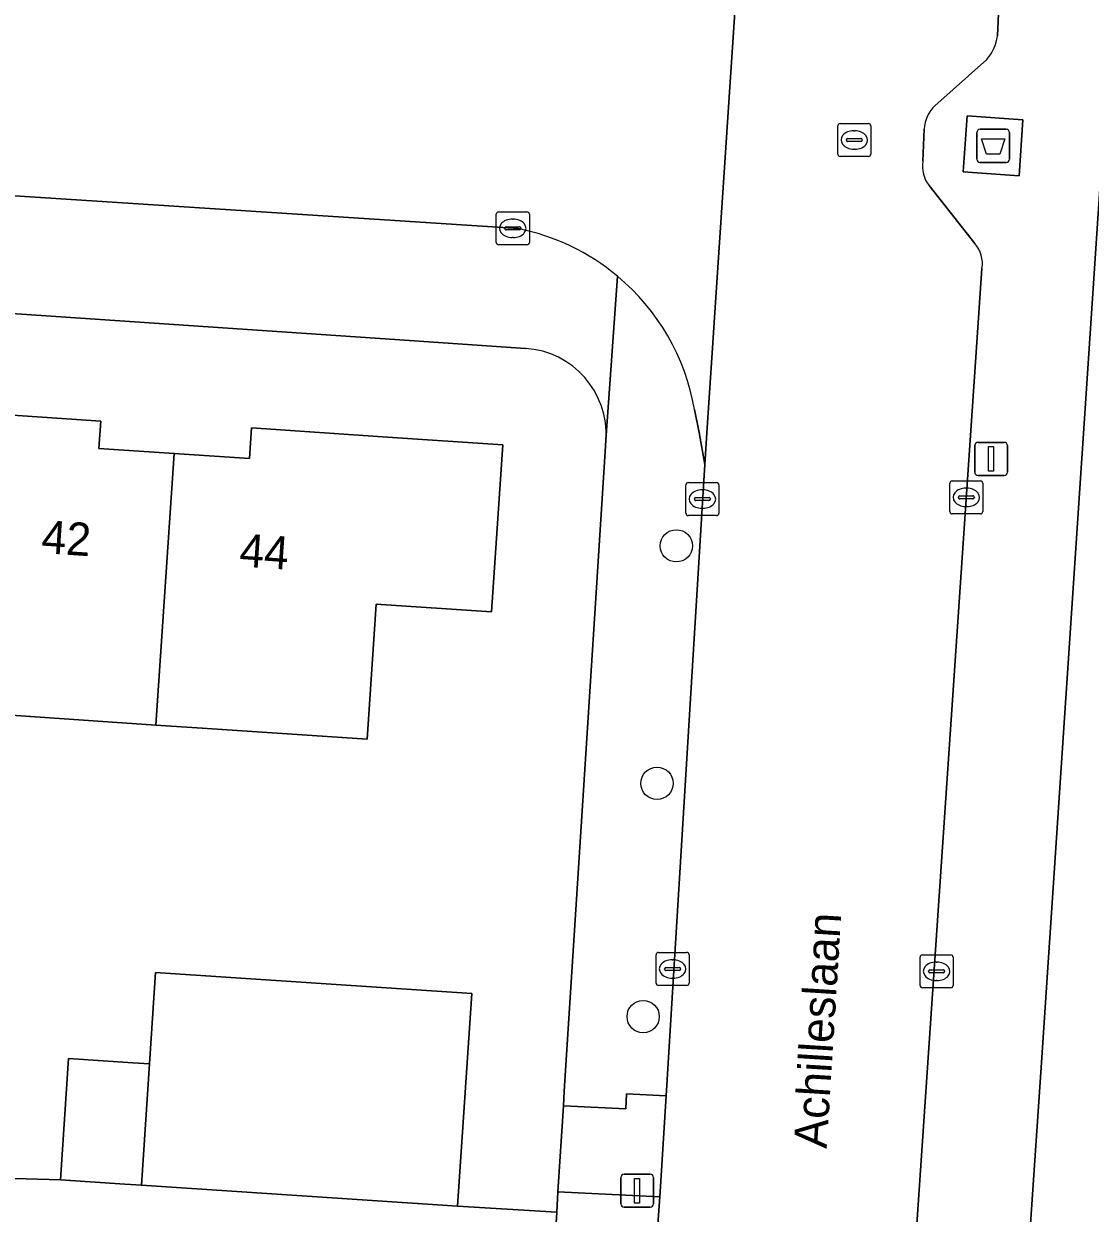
# Model space of a CAD drawing. Extents: x 161848 to 162726, y 385382 to 386521.
# Drawn here: x 162412.92 to 162445.21, y 385424.82 to 385460.85 of the extents above; entities that cross this region are included whole.
import ezdxf

# ---------------------------------------------------------------- set-up
doc = ezdxf.new("R2010")
doc.units = 0
for name, color, linetype in [('IMGEO_Afval_apart_plaats', 7, 'Continuous'), ('IMGEO_Boom', 7, 'Continuous'), ('IMGEO_Erf', 7, 'Continuous'), ('IMGEO_Groenvoorziening', 7, 'Continuous'), ('IMGEO_Kolk', 7, 'Continuous'), ('IMGEO_Lichtmast', 7, 'Continuous'), ('IMGEO_Muur', 7, 'Continuous'), ('IMGEO_Openbare_ruimte_label', 7, 'Continuous'), ('IMGEO_Pand', 7, 'Continuous'), ('IMGEO_Pand_nummerreeks', 7, 'Continuous'), ('IMGEO_Rijbaan_lokaal_gesloten', 7, 'Continuous'), ('IMGEO_Rijbaan_lokaal_open', 7, 'Continuous'), ('IMGEO_Rioolput', 7, 'Continuous'), ('IMGEO_Voetpad_gesloten', 7, 'Continuous'), ('IMGEO_Voetpad_open', 7, 'Continuous')]:
    doc.layers.add(name, color=color, linetype=linetype)

msp = doc.modelspace()

# ---------------------------------------------------------------- linework, layer by layer
at = {"layer": 'IMGEO_Afval_apart_plaats'}
for p, q in [((162441.772, 385456.749), (162441.772, 385457.549)), ((162441.772, 385457.549), (162441.772, 385456.749)), ((162441.872, 385457.649), (162442.662, 385457.649)), ((162442.662, 385457.649), (162441.872, 385457.649)), ((162442.762, 385457.549), (162442.762, 385456.749)), ((162442.762, 385456.749), (162442.762, 385457.549)), ((162442.662, 385456.649), (162441.872, 385456.649)), ((162441.872, 385456.649), (162442.662, 385456.649))]:
    msp.add_line(p, q, dxfattribs=at)
msp.add_lwpolyline([(162441.915, 385457.363), (162442.619, 385457.363), (162442.47, 385456.893), (162442.064, 385456.893), (162441.915, 385457.363)], dxfattribs=at)
for centre, start, end in [((162441.872, 385457.549), 90, 180), ((162441.872, 385457.549), 90, 180), ((162442.662, 385457.549), 0, 90), ((162442.662, 385457.549), 360, 90), ((162441.872, 385456.749), 180, 270), ((162441.872, 385456.749), 180, 270), ((162442.662, 385456.749), 270, 0), ((162442.662, 385456.749), 270, 0)]:
    msp.add_arc(centre, 0.1, start, end, dxfattribs=at)
at = {"layer": 'IMGEO_Boom'}
for centre in [(162432.675, 385445.035), (162432.091, 385437.842), (162431.671, 385430.777)]:
    msp.add_circle(centre, 0.489, dxfattribs=at)
at = {"layer": 'IMGEO_Erf'}
for points in [[(162428.108, 385451.016), (162424.152, 385451.285), (162286.568, 385460.627), (162285.504, 385460.702)], [(162411.535, 385449.066), (162415.25, 385448.815), (162415.193, 385447.986), (162417.472, 385447.832), (162419.751, 385447.678), (162419.813, 385448.605), (162423.927, 385448.327), (162427.421, 385448.092), (162427.08, 385443.035), (162423.586, 385443.271), (162423.309, 385439.175), (162418.321, 385439.513), (162416.914, 385439.608), (162410.92, 385440.013)], [(162409.861, 385425.954), (162414.028, 385425.832), (162414.273, 385429.51), (162416.22, 385429.38), (162416.721, 385429.347), (162416.905, 385432.115), (162426.479, 385431.478), (162426.05, 385425.033), (162429.053, 385424.859), (162429.088, 385425.47), (162429.255, 385428.076), (162429.283, 385428.519), (162430.198, 385442.824), (162430.523, 385447.896), (162430.545, 385448.238)]]:
    msp.add_lwpolyline(points, dxfattribs=at)
msp.add_arc((162427.935, 385448.406), 2.616, 356.3175, 86.2002, dxfattribs=at)
at = {"layer": 'IMGEO_Groenvoorziening'}
msp.add_lwpolyline([(162442.468, 385394.33), (162457.836, 385394.534), (162458.175, 385399.31), (162453.986, 385399.573), (162458.022, 385457.834), (162445.688, 385458.726), (162443.737, 385429.387), (162442.256, 385407.756), (162441.458, 385395.367)], dxfattribs=at)
at = {"layer": 'IMGEO_Kolk'}
for p, q in [((162427.298, 385455.151), (162428.15, 385455.151)), ((162427.223, 385454.225), (162427.223, 385455.077)), ((162427.711, 385454.931), (162427.736, 385454.931)), ((162428.224, 385455.077), (162428.224, 385454.225)), ((162427.482, 385454.645), (162427.482, 385454.657)), ((162427.92, 385454.608), (162427.522, 385454.608)), ((162427.525, 385454.694), (162427.923, 385454.694)), ((162427.966, 385454.657), (162427.966, 385454.645)), ((162428.15, 385454.151), (162427.298, 385454.151)), ((162427.734, 385454.371), (162427.709, 385454.371)), ((162432.965, 385446.026), (162432.965, 385446.878)), ((162433.04, 385446.952), (162433.892, 385446.952)), ((162433.966, 385446.878), (162433.966, 385446.026)), ((162440.956, 385446.077), (162440.956, 385446.929)), ((162441.031, 385447.003), (162441.883, 385447.003)), ((162441.957, 385446.929), (162441.957, 385446.077)), ((162433.267, 385446.495), (162433.665, 385446.495)), ((162433.453, 385446.732), (162433.478, 385446.732)), ((162441.215, 385446.497), (162441.215, 385446.509)), ((162441.258, 385446.546), (162441.656, 385446.546)), ((162441.444, 385446.783), (162441.469, 385446.783)), ((162441.699, 385446.509), (162441.699, 385446.497)), ((162433.224, 385446.446), (162433.224, 385446.458)), ((162433.662, 385446.409), (162433.264, 385446.409)), ((162433.476, 385446.172), (162433.451, 385446.172)), ((162433.708, 385446.458), (162433.708, 385446.446)), ((162441.653, 385446.46), (162441.255, 385446.46)), ((162441.467, 385446.223), (162441.442, 385446.223)), ((162433.892, 385445.952), (162433.04, 385445.952)), ((162441.883, 385446.003), (162441.031, 385446.003)), ((162432.06, 385431.794), (162432.06, 385432.646)), ((162432.135, 385432.72), (162432.987, 385432.72)), ((162432.548, 385432.5), (162432.573, 385432.5)), ((162433.061, 385432.646), (162433.061, 385431.794)), ((162440.054, 385431.723), (162440.054, 385432.575)), ((162440.129, 385432.649), (162440.981, 385432.649)), ((162441.055, 385432.575), (162441.055, 385431.723)), ((162432.319, 385432.214), (162432.319, 385432.226)), ((162432.757, 385432.177), (162432.359, 385432.177)), ((162432.362, 385432.263), (162432.76, 385432.263)), ((162432.803, 385432.226), (162432.803, 385432.214)), ((162440.313, 385432.143), (162440.313, 385432.155)), ((162440.751, 385432.106), (162440.353, 385432.106)), ((162440.356, 385432.192), (162440.754, 385432.192)), ((162440.542, 385432.429), (162440.567, 385432.429)), ((162440.797, 385432.155), (162440.797, 385432.143)), ((162432.987, 385431.72), (162432.135, 385431.72)), ((162432.571, 385431.94), (162432.546, 385431.94)), ((162440.565, 385431.869), (162440.54, 385431.869)), ((162440.981, 385431.649), (162440.129, 385431.649))]:
    msp.add_line(p, q, dxfattribs=at)
for points in [[(162427.298, 385455.151), (162428.15, 385455.151)], [(162427.223, 385454.225), (162427.223, 385455.077)], [(162428.224, 385455.077), (162428.224, 385454.225)], [(162428.15, 385454.151), (162427.298, 385454.151)], [(162432.965, 385446.026), (162432.965, 385446.878)], [(162433.04, 385446.952), (162433.892, 385446.952)], [(162433.966, 385446.878), (162433.966, 385446.026)], [(162440.956, 385446.077), (162440.956, 385446.929)], [(162441.031, 385447.003), (162441.883, 385447.003)], [(162441.957, 385446.929), (162441.957, 385446.077)], [(162433.892, 385445.952), (162433.04, 385445.952)], [(162441.883, 385446.003), (162441.031, 385446.003)], [(162432.06, 385431.794), (162432.06, 385432.646)], [(162432.135, 385432.72), (162432.987, 385432.72)], [(162433.061, 385432.646), (162433.061, 385431.794)], [(162440.054, 385431.723), (162440.054, 385432.575)], [(162440.129, 385432.649), (162440.981, 385432.649)], [(162441.055, 385432.575), (162441.055, 385431.723)], [(162432.987, 385431.72), (162432.135, 385431.72)], [(162440.981, 385431.649), (162440.129, 385431.649)]]:
    msp.add_lwpolyline(points, dxfattribs=at)
for centre, radius, start, end in [((162427.3, 385455.075), 0.0765, 91.552, 178.448), ((162427.3, 385455.075), 0.0765, 91.552, 178.448), ((162428.148, 385455.075), 0.0765, 1.552, 88.448), ((162428.148, 385455.075), 0.0765, 1.552, 88.448), ((162427.522, 385454.654), 0.0403, 85.8775, 175.7526), ((162427.519, 385454.644), 0.0366, 178.938, 274.7102), ((162427.923, 385454.651), 0.043, 264.8664, 352.4533), ((162427.927, 385454.656), 0.0386, 1.7309, 96.639), ((162427.3, 385454.227), 0.0765, 181.552, 268.448), ((162427.3, 385454.227), 0.0765, 181.552, 268.448), ((162428.148, 385454.227), 0.0765, 271.552, 358.448), ((162428.148, 385454.227), 0.0765, 271.552, 358.448), ((162433.042, 385446.876), 0.0765, 91.552, 178.448), ((162433.042, 385446.876), 0.0765, 91.552, 178.448), ((162433.89, 385446.876), 0.0765, 1.552, 88.448), ((162433.89, 385446.876), 0.0765, 1.552, 88.448), ((162441.033, 385446.927), 0.0765, 91.552, 178.448), ((162441.033, 385446.927), 0.0765, 91.552, 178.448), ((162441.881, 385446.927), 0.0765, 1.552, 88.448), ((162441.881, 385446.927), 0.0765, 1.552, 88.448), ((162433.264, 385446.455), 0.0403, 85.8775, 175.7526), ((162433.669, 385446.457), 0.0386, 1.7309, 96.639), ((162441.255, 385446.506), 0.0403, 85.8775, 175.7526), ((162441.252, 385446.496), 0.0366, 178.938, 274.7102), ((162441.656, 385446.503), 0.043, 264.8664, 352.4533), ((162441.66, 385446.508), 0.0386, 1.7309, 96.639), ((162433.261, 385446.445), 0.0366, 178.938, 274.7102), ((162433.665, 385446.452), 0.043, 264.8664, 352.4533), ((162433.042, 385446.028), 0.0765, 181.552, 268.448), ((162433.042, 385446.028), 0.0765, 181.552, 268.448), ((162433.89, 385446.028), 0.0765, 271.552, 358.448), ((162433.89, 385446.028), 0.0765, 271.552, 358.448), ((162441.033, 385446.079), 0.0765, 181.552, 268.448), ((162441.033, 385446.079), 0.0765, 181.552, 268.448), ((162441.881, 385446.079), 0.0765, 271.552, 358.448), ((162441.881, 385446.079), 0.0765, 271.552, 358.448), ((162432.137, 385432.644), 0.0765, 91.552, 178.448), ((162432.137, 385432.644), 0.0765, 91.552, 178.448), ((162432.985, 385432.644), 0.0765, 1.552, 88.448), ((162432.985, 385432.644), 0.0765, 1.552, 88.448), ((162440.131, 385432.573), 0.0765, 91.552, 178.448), ((162440.131, 385432.573), 0.0765, 91.552, 178.448), ((162440.979, 385432.573), 0.0765, 1.552, 88.448), ((162440.979, 385432.573), 0.0765, 1.552, 88.448), ((162432.359, 385432.223), 0.0403, 85.8775, 175.7526), ((162432.356, 385432.213), 0.0366, 178.938, 274.7102), ((162432.76, 385432.22), 0.043, 264.8664, 352.4533), ((162432.764, 385432.225), 0.0386, 1.7309, 96.639), ((162440.353, 385432.152), 0.0403, 85.8775, 175.7526), ((162440.35, 385432.142), 0.0366, 178.938, 274.7102), ((162440.754, 385432.149), 0.043, 264.8664, 352.4533), ((162440.758, 385432.154), 0.0386, 1.7309, 96.639), ((162432.137, 385431.796), 0.0765, 181.552, 268.448), ((162432.137, 385431.796), 0.0765, 181.552, 268.448), ((162432.985, 385431.796), 0.0765, 271.552, 358.448), ((162432.985, 385431.796), 0.0765, 271.552, 358.448), ((162440.131, 385431.725), 0.0765, 181.552, 268.448), ((162440.131, 385431.725), 0.0765, 181.552, 268.448), ((162440.979, 385431.725), 0.0765, 271.552, 358.448), ((162440.979, 385431.725), 0.0765, 271.552, 358.448)]:
    msp.add_arc(centre, radius, start, end, dxfattribs=at)
for centre, major_axis, ratio, start_param, end_param in [((162427.71, 385454.651), (-0.387, 0.002), 0.722429, 4.712389, 7.853982), ((162427.735, 385454.651), (-0.39, 0.002), 0.717154, 1.570796, 4.712389), ((162433.452, 385446.452), (-0.387, 0.002), 0.722429, 4.712389, 7.853982), ((162433.477, 385446.452), (-0.39, 0.002), 0.717154, 1.570796, 4.712389), ((162441.443, 385446.503), (-0.387, 0.002), 0.722429, 4.712389, 7.853982), ((162441.468, 385446.503), (-0.39, 0.002), 0.717154, 1.570796, 4.712389), ((162432.547, 385432.22), (-0.387, 0.002), 0.722429, 4.712389, 7.853982), ((162432.572, 385432.22), (-0.39, 0.002), 0.717154, 1.570796, 4.712389), ((162440.541, 385432.149), (-0.387, 0.002), 0.722429, 4.712389, 7.853982), ((162440.566, 385432.149), (-0.39, 0.002), 0.717154, 1.570796, 4.712389)]:
    msp.add_ellipse(centre, major_axis=major_axis, ratio=ratio, start_param=start_param, end_param=end_param, dxfattribs=at)
at = {"layer": 'IMGEO_Lichtmast'}
for p, q in [((162441.711, 385447.269), (162441.711, 385448.069)), ((162441.711, 385448.069), (162441.711, 385447.269)), ((162441.811, 385448.169), (162442.601, 385448.169)), ((162442.601, 385448.169), (162441.811, 385448.169)), ((162442.701, 385448.069), (162442.701, 385447.269)), ((162442.701, 385447.269), (162442.701, 385448.069)), ((162442.601, 385447.169), (162441.811, 385447.169)), ((162441.811, 385447.169), (162442.601, 385447.169)), ((162431.092, 385426.004), (162431.882, 385426.004)), ((162431.882, 385426.004), (162431.092, 385426.004)), ((162430.992, 385425.104), (162430.992, 385425.904)), ((162430.992, 385425.904), (162430.992, 385425.104)), ((162431.982, 385425.904), (162431.982, 385425.104)), ((162431.982, 385425.104), (162431.982, 385425.904)), ((162431.882, 385425.004), (162431.092, 385425.004)), ((162431.092, 385425.004), (162431.882, 385425.004))]:
    msp.add_line(p, q, dxfattribs=at)
for points in [[(162442.131, 385448.044), (162442.281, 385448.044), (162442.281, 385447.294), (162442.131, 385447.294), (162442.131, 385448.044)], [(162431.412, 385425.879), (162431.562, 385425.879), (162431.562, 385425.129), (162431.412, 385425.129), (162431.412, 385425.879)]]:
    msp.add_lwpolyline(points, dxfattribs=at)
for centre, start, end in [((162441.811, 385448.069), 90, 180), ((162441.811, 385448.069), 90, 180), ((162442.601, 385448.069), 0, 90), ((162442.601, 385448.069), 360, 90), ((162441.811, 385447.269), 180, 270), ((162441.811, 385447.269), 180, 270), ((162442.601, 385447.269), 270, 0), ((162442.601, 385447.269), 270, 0), ((162431.092, 385425.904), 90, 180), ((162431.092, 385425.904), 90, 180), ((162431.882, 385425.904), 0, 90), ((162431.882, 385425.904), 360, 90), ((162431.092, 385425.104), 180, 270), ((162431.092, 385425.104), 180, 270), ((162431.882, 385425.104), 270, 0), ((162431.882, 385425.104), 270, 0)]:
    msp.add_arc(centre, 0.1, start, end, dxfattribs=at)
at = {"layer": 'IMGEO_Muur'}
for points in [[(162430.198, 385442.824), (162429.283, 385428.519)], [(162429.283, 385428.519), (162429.252, 385428.027)]]:
    msp.add_lwpolyline(points, dxfattribs=at)
at = {"layer": 'IMGEO_Pand'}
for points in [[(162417.472, 385447.832), (162415.193, 385447.986), (162415.25, 385448.815), (162411.535, 385449.066), (162410.92, 385440.013), (162416.914, 385439.608)], [(162416.914, 385439.608), (162418.321, 385439.513), (162423.309, 385439.175), (162423.586, 385443.271), (162427.08, 385443.035), (162427.421, 385448.092), (162423.927, 385448.327), (162419.813, 385448.605), (162419.751, 385447.678), (162417.472, 385447.832)], [(162416.721, 385429.347), (162416.476, 385425.669), (162426.05, 385425.033), (162426.479, 385431.478), (162416.905, 385432.115)], [(162416.721, 385429.347), (162416.22, 385429.38), (162414.273, 385429.51), (162414.028, 385425.832), (162415.971, 385425.703), (162416.476, 385425.669)]]:
    msp.add_lwpolyline(points, close=True, dxfattribs=at)
at = {"layer": 'IMGEO_Rijbaan_lokaal_gesloten'}
for points in [[(162450.162, 385577.468), (162450.352, 385579.883), (162442.418, 385580.396), (162442.248, 385577.631), (162439.944, 385543.379), (162439.699, 385539.748), (162437.017, 385500), (162434.834, 385467.105), (162434.805, 385466.668), (162433.595, 385448.457), (162433.536, 385447.496), (162432.367, 385428.377), (162432.18, 385425.321), (162430.698, 385404.895), (162430.353, 385400.004), (162435.988, 385399.644), (162436.331, 385400.107), (162438.143, 385401.743)], [(162442.399, 385460.482), (162442.465, 385461.839), (162450.162, 385577.468)], [(162440.499, 385458.359), (162442.075, 385459.767)], [(162440.142, 385456.685), (162440.179, 385457.656)], [(162441.717, 385454.191), (162440.327, 385455.943)], [(162438.47, 385402.537), (162438.88, 385408.614), (162441.752, 385450.9), (162441.931, 385453.431)]]:
    msp.add_lwpolyline(points, dxfattribs=at)
for centre, radius, start, end in [((162441.013, 385460.679), 1.4, 319.3387, 351.9063), ((162441.257, 385457.589), 1.08, 134.582, 176.4687), ((162441.096, 385456.529), 0.967, 170.7029, 217.2969), ((162441.017, 385453.584), 0.926, 350.504, 40.9482)]:
    msp.add_arc(centre, radius, start, end, dxfattribs=at)
at = {"layer": 'IMGEO_Rijbaan_lokaal_open'}
for points in [[(162433.228, 385449.165), (162433.371, 385448.464), (162433.536, 385447.496), (162433.595, 385448.457), (162434.805, 385466.668), (162434.834, 385467.105), (162434.504, 385465.962)], [(162285.815, 385464.092), (162334.512, 385460.716), (162340.453, 385460.328), (162358.028, 385459.18), (162427.882, 385454.643)]]:
    msp.add_lwpolyline(points, dxfattribs=at)
for centre, radius, start, end in [((162426.551, 385448.001), 6.774, 50.1684, 78.6685), ((162426.549, 385447.993), 6.781, 9.9481, 50.1935)]:
    msp.add_arc(centre, radius, start, end, dxfattribs=at)
at = {"layer": 'IMGEO_Rioolput'}
for p, q in [((162437.564, 385456.9), (162437.564, 385457.752)), ((162437.639, 385457.826), (162438.491, 385457.826)), ((162438.565, 385457.752), (162438.565, 385456.9)), ((162437.823, 385457.32), (162437.823, 385457.332)), ((162437.866, 385457.369), (162438.264, 385457.369)), ((162438.052, 385457.606), (162438.077, 385457.606)), ((162438.307, 385457.332), (162438.307, 385457.32)), ((162438.261, 385457.283), (162437.863, 385457.283)), ((162438.075, 385457.046), (162438.05, 385457.046)), ((162438.491, 385456.826), (162437.639, 385456.826))]:
    msp.add_line(p, q, dxfattribs=at)
for points in [[(162437.564, 385456.9), (162437.564, 385457.752)], [(162437.639, 385457.826), (162438.491, 385457.826)], [(162438.565, 385457.752), (162438.565, 385456.9)], [(162438.491, 385456.826), (162437.639, 385456.826)]]:
    msp.add_lwpolyline(points, dxfattribs=at)
for centre, radius, start, end in [((162437.641, 385457.75), 0.0765, 91.552, 178.448), ((162437.641, 385457.75), 0.0765, 91.552, 178.448), ((162438.489, 385457.75), 0.0765, 1.552, 88.448), ((162438.489, 385457.75), 0.0765, 1.552, 88.448), ((162437.863, 385457.329), 0.0403, 85.8775, 175.7526), ((162437.86, 385457.319), 0.0366, 178.938, 274.7102), ((162438.264, 385457.326), 0.043, 264.8664, 352.4533), ((162438.268, 385457.331), 0.0386, 1.7309, 96.639), ((162437.641, 385456.902), 0.0765, 181.552, 268.448), ((162437.641, 385456.902), 0.0765, 181.552, 268.448), ((162438.489, 385456.902), 0.0765, 271.552, 358.448), ((162438.489, 385456.902), 0.0765, 271.552, 358.448)]:
    msp.add_arc(centre, radius, start, end, dxfattribs=at)
for centre, major_axis, ratio, start_param, end_param in [((162438.051, 385457.326), (-0.387, 0.002), 0.722429, 4.712389, 7.853982), ((162438.076, 385457.326), (-0.39, 0.002), 0.717154, 1.570796, 4.712389)]:
    msp.add_ellipse(centre, major_axis=major_axis, ratio=ratio, start_param=start_param, end_param=end_param, dxfattribs=at)
at = {"layer": 'IMGEO_Voetpad_gesloten'}
msp.add_lwpolyline([(162443.17, 385457.939), (162441.479, 385458.054), (162441.364, 385456.359), (162443.055, 385456.244)], close=True, dxfattribs=at)
at = {"layer": 'IMGEO_Voetpad_open'}
for points in [[(162442.256, 385407.756), (162443.737, 385429.387), (162445.688, 385458.726), (162445.849, 385461.151), (162446.446, 385469.756), (162446.676, 385473.196), (162448.539, 385500), (162450.031, 385521.458), (162450.405, 385526.588), (162450.744, 385531.817), (162452.649, 385560.747), (162452.933, 385565.323), (162454.648, 385591.147), (162455.021, 385596.06), (162455.065, 385596.685), (162455.738, 385606.152), (162455.776, 385606.687), (162452.208, 385607.27), (162451.787, 385601.362), (162451.635, 385598.888), (162450.352, 385579.883), (162450.162, 385577.468), (162442.465, 385461.839), (162442.399, 385460.482)], [(162427.882, 385454.643), (162358.028, 385459.18), (162340.453, 385460.328), (162334.512, 385460.716), (162285.815, 385464.092)], [(162285.504, 385460.702), (162286.568, 385460.627), (162424.152, 385451.285), (162428.108, 385451.016)], [(162442.075, 385459.767), (162440.499, 385458.359)], [(162440.179, 385457.656), (162440.142, 385456.685)], [(162440.327, 385455.943), (162441.717, 385454.191)], [(162441.931, 385453.431), (162441.752, 385450.9), (162438.88, 385408.614), (162438.47, 385402.537)], [(162430.89, 385453.203), (162430.545, 385448.238), (162430.523, 385447.896), (162430.198, 385442.824), (162429.283, 385428.519), (162429.255, 385428.076), (162431.141, 385427.985), (162431.168, 385428.435), (162432.367, 385428.377), (162433.536, 385447.496)], [(162430.545, 385448.238), (162430.89, 385453.203)], [(162433.536, 385447.496), (162433.371, 385448.464), (162433.228, 385449.165)], [(162280.836, 385433.091), (162428.958, 385423.219), (162429.053, 385424.859), (162426.05, 385425.033), (162416.476, 385425.669), (162415.971, 385425.703), (162414.028, 385425.832), (162409.861, 385425.954), (162404.208, 385426.258), (162401.284, 385426.416), (162398.524, 385426.565), (162395.223, 385426.793), (162395.237, 385427.18), (162392.289, 385427.289), (162390.12, 385427.37), (162383.076, 385427.896)], [(162430.353, 385400.004), (162430.698, 385404.895), (162432.18, 385425.321), (162429.088, 385425.47), (162429.053, 385424.859), (162428.958, 385423.219), (162427.854, 385404.175), (162427.325, 385397.116)]]:
    msp.add_lwpolyline(points, dxfattribs=at)
for points in [[(162441.364, 385456.359), (162441.479, 385458.054), (162443.17, 385457.939), (162443.055, 385456.244)], [(162432.367, 385428.377), (162431.168, 385428.435), (162431.141, 385427.985), (162429.255, 385428.076), (162429.088, 385425.47), (162432.18, 385425.321)]]:
    msp.add_lwpolyline(points, close=True, dxfattribs=at)
for centre, radius, start, end in [((162441.013, 385460.679), 1.4, 319.3387, 351.9063), ((162441.257, 385457.589), 1.08, 134.582, 176.4687), ((162441.096, 385456.529), 0.967, 170.7029, 217.2969), ((162426.551, 385448.001), 6.774, 50.1684, 78.6685), ((162441.017, 385453.584), 0.926, 350.504, 40.9482), ((162426.549, 385447.993), 6.781, 9.9481, 50.1935), ((162427.935, 385448.406), 2.616, 356.3175, 86.2002)]:
    msp.add_arc(centre, radius, start, end, dxfattribs=at)

# ---------------------------------------------------------------- texts
at = {"layer": 'IMGEO_Openbare_ruimte_label'}
msp.add_text('Achilleslaan', height=1, rotation=86.4451, dxfattribs=at).set_placement((162437.227, 385426.769))
at = {"layer": 'IMGEO_Pand_nummerreeks'}
for s, p in [('42', (162413.43, 385444.819)), ('44', (162419.424, 385444.413))]:
    msp.add_text(s, height=1, rotation=356.1224, dxfattribs=at).set_placement(p)

doc.saveas('drawing.dxf')
